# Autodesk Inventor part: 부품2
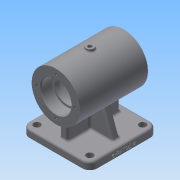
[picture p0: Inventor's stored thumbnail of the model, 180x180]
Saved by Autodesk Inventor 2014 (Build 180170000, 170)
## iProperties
Created: 2019-06
Part Number: 부품2
Material: 일반
Document SubType Name: Modeling
Designer: net
Density: 1 g/cm^3
Appearance: 기본값
Mass: 225.741 g
Surface Area: 624.818 cm^2
Volume: 225.741 cm^3
Author: net
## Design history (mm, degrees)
sketch "스케치1"
  geometry: L1 (-45, 0)-(45, 0); L2 (-45, 32)-(-45, -32); L3 (-45, 32)-(45, 32); L4 (45, 32)-(45, 0); L5 (-45, 20)-(-45, -20); L6 (-45, 20)-(-30, 20); L7 (-30, 20)-(-30, 0); L8 (-30, 17)-(-30, -17); L9 (-30, 17)-(-24, 17); L10 (-24, 17)-(-24, 0); L11 (-24, 25)-(-24, -25); L12 (-24, 25)-(24, 25); L13 (24, 25)-(24, 0); L14 (24, 17)-(24, -17); L15 (24, 17)-(30, 17); L16 (30, 17)-(30, 0); L17 (30, 20)-(30, -20); L18 (30, 20)-(45, 20); L19 (45, 20)-(45, 0); L20 (45, 0)-(-45, 0); 2 further points
  constraints: 40 end point, 13 perpendicular, 7 midpoint, 6 point on line, 4 collinear, 1 coincident, 1 horizontal, 1 parallel, 1 vertical
  dimensions: "d0" = 90 distance of L1.start L1.end; "d1" = 64 distance of L2.start L2.end; "d2" = 40 distance of L5.start L5.end; "d3" = 15 distance of L5.start L6.end; "d4" = 34 distance of L8.start L8.end; "d5" = 6 distance of L8.start L9.end; "d6" = 50 distance of L11.start L11.end; "d7" = 48 distance of L11.start L12.end; "d9" = 34 distance of L14.start L14.end; "d10" = 6 distance of L14.start L15.end; "d11" = 40 distance of L17.start L17.end
revolve "회전1" sketch "스케치1" stored, may be unused: angle "d12" = 90 deg
node "작업 평면1"
sketch "스케치2"
  geometry: L1 (0, 0)-(0, -65); C1 r 25 at (0, 0) reference; C2 r 32 at (0, 0) reference; 1 further point
  constraints: 2 end point, 1 vertical
  dimensions: "d13" = 65 distance of L1.start L1.end
  node "절단 모서리 투영1"
node "작업 평면2"
sketch "스케치3"
  geometry: L1 (45, -45)-(-45, -45); L2 (-45, -45)-(-45, 45); L3 (-45, 45)-(45, 45); L4 (45, 45)-(45, -45); L5 (45, -45)-(-45, 45); L6 (-45, -45)-(45, 45); 2 further points
  constraints: 12 end point, 2 midpoint, 2 parallel, 1 horizontal, 1 perpendicular
  dimensions: "d14" = 90 distance of L1.end L2.end; "d15" = 90 distance of L2.end L3.end
extrude "돌출1" join sketch "스케치3" distance "d16" = 10; taper "d17" = 0 deg
sketch "스케치4"
  geometry: L1 (-45, -45)-(45, -45) reference; L2 (-45, 45)-(-45, -45) reference; L3 (-35, -5)-(35, -5); L4 (35, -5)-(35, 5); L5 (35, 5)-(-35, 5); L6 (-35, 5)-(-35, -5); L7 (-35, -5)-(35, 5); L8 (35, -5)-(-35, 5); L9 (-5, -35)-(5, -35); L10 (5, -35)-(5, 35); L11 (5, 35)-(-5, 35); L12 (-5, 35)-(-5, -35); L13 (-5, -35)-(5, 35); L14 (5, -35)-(-5, 35); 3 further points
  constraints: 24 end point, 6 midpoint, 4 parallel, 2 horizontal, 2 perpendicular
  dimensions: "d18" = 10 distance of L10.end L11.end; "d19" = 10 distance between parallel lines of L1 L9; "d20" = 10 distance of L3.end L4.end; "d21" = 10 distance between parallel lines of L2 L6
extrude "돌출2" join sketch "스케치4" stored distance "d22" = 10; taper "d23" = 0 deg
sketch "스케치5"
  geometry: L1 (-45, -65)-(-45, -55) reference; L2 (-45, -55)-(-5, -55) reference; L3 (-5, -55)-(-5, -31.607) reference; L4 (5, -31.607)-(5, -55) reference; L5 (5, -55)-(45, -55) reference; L6 (45, -55)-(45, -65) reference; L7 (45, -65)-(-45, -65) reference; L8 (-45, -55)-(-35, -55); L9 (45, -55)-(35, -55); L10 (-35, -55)-(-5, -55); L11 (-5, -31.607)-(-5, -55); L12 (5, -31.607)-(5, -55); L13 (35, -55)-(5, -55); L14 (35, -55)-(23.058, -22.189); L15 (-35, -55)-(-23.058, -22.189); C1 r 25 at (0, 0) reference; A1 r 32 centre (0, 0) between (5, -31.607) and (-5, -31.607) reference; A2 r 32 centre (0, 0) between (-23.058, -22.189) and (-5, -31.607); A3 r 32 centre (0, 0) between (5, -31.607) and (23.058, -22.189); 1 further point
  constraints: 16 end point, 6 point on circle, 2 centre point, 2 concentric, 2 perpendicular, 2 point on line, 1 collinear, 1 parallel
  dimensions: "d24" = 10 distance of L1.end L8.end; "d25" = 10 distance of L5.end L9.end; "d28" = 110 deg angle of L8 L15; "d29" = 110 deg angle of L5 L14
extrude "돌출3" join sketch "스케치5" stored distance "d30" = 10; taper "d31" = 0 deg
sketch "스케치6" dims "d32" = 50
  geometry: L1 (-45, -65)-(45, -65) reference; C1 r 32 at (0, 0) reference; 2 further points
  constraints: 1 coincident, 1 vertical alignment, 2 other
  dimensions: "d33" = 90 distance from line of L1 point (0, 25)
hole "구멍1" sketch "스케치6" at (0, 25) diameter "d34" = 3.242; stored, may be unused: countersink angle "d38" = 90 deg, drill point angle "d40" = 118 deg; dims "d35" = 7, "d36" = 4, "d37" = 2, "d39" = 9
sketch "스케치7" dims "d44" = 50
  geometry: L1 (45, 65)-(-45, 65) reference; C1 r 32 at (0, 0) reference; 2 further points
  constraints: 1 coincident, 1 vertical alignment, 2 other
  dimensions: "d45" = 90 distance from line of point (0, -25) L1
hole "구멍2" sketch "스케치7" at (0, -25) diameter "d46" = 3.242; stored, may be unused: countersink angle "d50" = 90 deg, drill point angle "d52" = 118 deg; dims "d47" = 7, "d48" = 4, "d49" = 2, "d51" = 9
sketch "스케치8"
  geometry: L1 (30, -20)-(45, -20) reference; L2 (45, -20)-(45, -23.379) reference; L3 (45, -23.379)-(36, -23.379) reference; L4 (36, -23.379)-(35.026, -25) reference; L5 (35.026, -25)-(36, -26.621) reference; L6 (36, -26.621)-(45, -26.621) reference; L7 (45, -26.621)-(45, -32) reference; L8 (45, -32)-(35, -32) reference; L9 (35, -32)-(35, -55) reference; L10 (35, -55)-(45, -55) reference; L11 (45, -55)-(45, -65) reference; L12 (45, -65)-(-45, -65) reference; L13 (-45, -65)-(-45, -55) reference; L14 (-45, -55)-(-35, -55) reference; L15 (-35, -55)-(-35, -32) reference; L16 (-35, -32)-(-45, -32) reference; L17 (-45, -32)-(-45, -26.621) reference; L18 (-45, -26.621)-(-36, -26.621) reference; L19 (-36, -26.621)-(-35.026, -25) reference; L20 (-35.026, -25)-(-36, -23.379) reference; L21 (-36, -23.379)-(-45, -23.379) reference; L22 (-45, -23.379)-(-45, -20) reference; L23 (-45, -20)-(-30, -20) reference; L24 (-30, -20)-(-30, -17) reference; L25 (-30, -17)-(-24, -17) reference; L26 (-24, -17)-(-24, -25) reference; L27 (-24, -25)-(24, -25) reference; L28 (24, -25)-(24, -17) reference; L29 (24, -17)-(30, -17) reference; L30 (30, -17)-(30, -20) reference; L31 (-45, 32)-(45, 32) reference; L32 (45, 32)-(45, 26.621) reference; L33 (45, 26.621)-(36, 26.621) reference; L34 (36, 26.621)-(35.026, 25) reference; L35 (35.026, 25)-(36, 23.379) reference; L36 (36, 23.379)-(45, 23.379) reference; L37 (45, 23.379)-(45, 20) reference; L38 (45, 20)-(30, 20) reference; L39 (30, 20)-(30, 17) reference; L40 (30, 17)-(24, 17) reference; L41 (24, 17)-(24, 25) reference; L42 (24, 25)-(-24, 25) reference; L43 (-24, 25)-(-24, 17) reference; L44 (-24, 17)-(-30, 17) reference; L45 (-30, 17)-(-30, 20) reference; L46 (-30, 20)-(-45, 20) reference; L47 (-45, 20)-(-45, 23.379) reference; L48 (-45, 23.379)-(-36, 23.379) reference; L49 (-36, 23.379)-(-35.026, 25) reference; L50 (-35.026, 25)-(-36, 26.621) reference; L51 (-36, 26.621)-(-45, 26.621) reference; L52 (-45, 26.621)-(-45, 32) reference; L53 (-45, -20)-(-45, 20) reference; L54 (-45, 0)-(0, 0); L55 (0, 0)-(0, 35)
  constraints: 4 end point, 2 perpendicular, 1 midpoint
  dimensions: "d56" = 35 distance of L54.end L55.end
  node "절단 모서리 투영3"
node "작업 평면3"
sketch "스케치9"
  geometry: C1 r 5 at (0, 0); 2 further points
  constraints: 1 centre point, 1 coincident
  dimensions: "d57" = 10 diameter of C1
extrude "돌출4" join sketch "스케치9" stored distance "d58" = 10; taper "d59" = 0 deg
sketch "스케치10"
  geometry: C1 r 5 at (0, 0) reference; 1 further point
  constraints: 1 coincident
hole "구멍3" sketch "스케치10" at (0, 0) diameter "d60" = 4.917; stored, may be unused: countersink angle "d64" = 90 deg, drill point angle "d66" = 0 deg; dims "d61" = 7, "d62" = 4, "d63" = 2, "d65" = 9
fillet "모깎기1" dims "d67" = 3
fillet "모깎기2" dims "d68" = 10
fillet "모깎기3" dims "d69" = 3
fillet "모깎기4" dims "d70" = 3
sketch "스케치11"
  geometry: A1 r 7 centre (35, -35) between (35, -42) and (42, -35) reference; A2 r 7 centre (35, 35) between (42, 35) and (35, 42) reference; A3 r 7 centre (-35, 35) between (-35, 42) and (-42, 35) reference; A4 r 7 centre (-35, -35) between (-42, -35) and (-35, -42) reference; 5 further points
  constraints: 4 coincident
hole "구멍4" sketch "스케치11" at (-35, 35), (35, 35), (35, -35), (-35, -35) diameter "d71" = 9; stored, may be unused: countersink angle "d75" = 90 deg, drill point angle "d77" = 0 deg; dims "d72" = 7, "d73" = 4, "d74" = 2, "d76" = 9
fillet "모깎기5" dims "d78" = 2
fillet "모깎기6" dims "d79" = 0.6
chamfer "모따기1" distance "d80" = 1; stored, may be unused: second distance "d81" = 2, angle "d82" = 45 deg
sketch "스케치12"
  geometry: L1 (-35, 45)-(35, 45) reference; L2 (-45, -35)-(-45, 35) reference; L3 (35, -45)-(-35, -45) reference; L4 (45, 35)-(45, -35) reference; L5 (22.155, -40)-(-22.155, -40); L6 (-40, -22.155)-(-40, 22.155); L7 (-22.155, 40)-(22.155, 40); L8 (40, 22.155)-(40, -22.155); L9 (40, -40)-(-40, 40); L10 (-40, -40)-(40, 40); A1 r 10 centre (35, 35) between (45, 35) and (35, 45) reference; A2 r 10 centre (-35, 35) between (-35, 45) and (-45, 35) reference; A3 r 10 centre (-35, -35) between (-45, -35) and (-35, -45) reference; A4 r 10 centre (35, -35) between (35, -45) and (45, -35) reference; A5 r 10 centre (-35, -35) between (-25.119, -36.538) and (-36.538, -25.119); A6 r 10 centre (35, -35) between (36.538, -25.119) and (25.119, -36.538); A7 r 10 centre (35, 35) between (25.119, 36.538) and (36.538, 25.119); A8 r 10 centre (-35, 35) between (-36.538, 25.119) and (-25.119, 36.538); A9 r 10 centre (-35, 35) between (-35, 45) and (-42.071, 42.071); A10 r 10 centre (-35, 35) between (-43.66, 40) and (-45, 35); A11 r 3 centre (-37, -22.155) between (-40, -22.155) and (-36.538, -25.119); A12 r 3 centre (-22.155, -37) between (-25.119, -36.538) and (-22.155, -40); A13 r 3 centre (22.155, -37) between (22.155, -40) and (25.119, -36.538); A14 r 3 centre (37, -22.155) between (36.538, -25.119) and (40, -22.155); A15 r 3 centre (37, 22.155) between (40, 22.155) and (36.538, 25.119); A16 r 3 centre (22.155, 37) between (25.119, 36.538) and (22.155, 40); A17 r 3 centre (-22.155, 37) between (-22.155, 40) and (-25.119, 36.538); A18 r 3 centre (-37, 22.155) between (-36.538, 25.119) and (-40, 22.155); 9 further points
  constraints: 36 point on circle, 17 end point, 16 tangent, 14 centre point, 10 point on line, 7 equal radius, 4 coincident, 2 midpoint, 2 parallel, 1 horizontal, 1 perpendicular
  dimensions: "d83" = 80 distance of L10.start L9.end; "d84" = 80 distance of L9.end L10.end; "d89" = 3 radius of A11
extrude "돌출5" cut sketch "스케치12" distance "d90" = 5; taper "d91" = 0 deg
sketch "스케치13"
  geometry: L1 (0, 0)-(0, 70) reference; L2 (-7, -10)-(0, -10) reference; 2 further points
  constraints: 1 other
  dimensions: "d92" = 4 distance from line of L1 point (-4, 35); "d93" = 45 distance from line of L2 point (-4, 35)
feature "엠보싱1" sketch "스케치13" dims "d0" = 90, "d1" = 64, "d2" = 40, "d3" = 15, "d4" = 34, "d5" = 6, "d6" = 50, "d7" = 48, "d9" = 34, "d10" = 6, "d11" = 40, "d94" = 0.5, "d95" = 0
node "솔리드1"
pattern_circular "원형 패턴1" dims angle "d42" = 360 deg
pattern_circular "원형 패턴2" dims angle "d54" = 360 deg
node "절단 모서리 투영2"
other parameters: "d26" = 110 deg, "d27" = 110 deg
